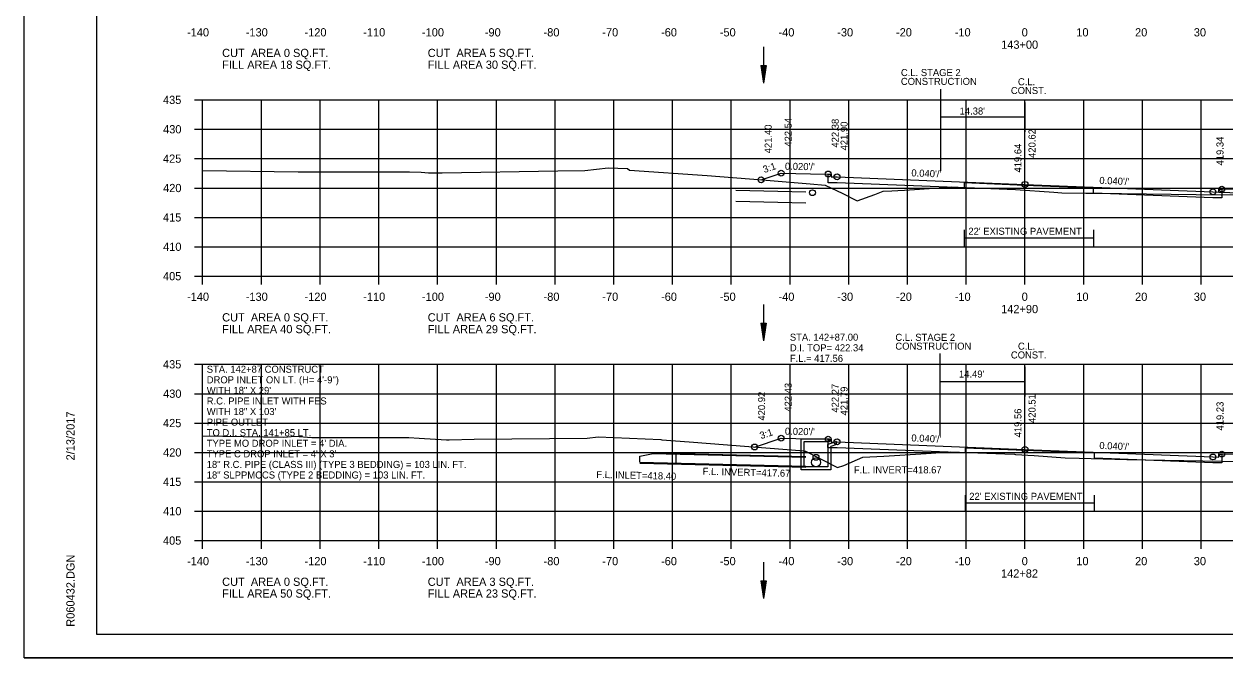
# Model space of a CAD drawing. Extents: x 1538688 to 1540766, y 656250 to 671912.
# Drawn here: x 1538687.8 to 1538892.2, y 662738 to 662845.9 of the extents above; entities that cross this region are included whole.
import ezdxf

# ---------------------------------------------------------------- set-up
doc = ezdxf.new("R2010")
doc.units = 0
for name, color, linetype in [('15', 7, 'Continuous'), ('16', 7, 'Continuous'), ('18', 7, 'Continuous'), ('20', 7, 'Continuous'), ('22', 7, 'Continuous'), ('26', 7, 'Continuous'), ('39', 7, 'Continuous'), ('40', 7, 'Continuous'), ('41', 7, 'Continuous'), ('42', 7, 'Continuous'), ('7', 7, 'Continuous'), ('Borings', 7, 'Continuous'), ('Default', 7, 'Continuous'), ('Horizontal Alignment', 7, 'Continuous'), ('RipRap', 7, 'Continuous'), ('Wall Heights', 7, 'Continuous')]:
    doc.layers.add(name, color=color, linetype=linetype)

msp = doc.modelspace()

# ---------------------------------------------------------------- linework, layer by layer
at = {"layer": '15'}
for p, q in [((1538813.19, 662838.88), (1538813.64, 662835.88)), ((1538813.19, 662838.88), (1538814.09, 662838.88)), ((1538813.27, 662838.88), (1538813.64, 662836.38)), ((1538813.34, 662838.88), (1538813.64, 662836.9)), ((1538813.42, 662838.88), (1538813.64, 662837.4)), ((1538813.5, 662838.88), (1538813.64, 662837.91)), ((1538813.57, 662838.88), (1538813.64, 662838.41)), ((1538814.09, 662838.88), (1538813.64, 662835.88)), ((1538813.79, 662838.88), (1538813.64, 662837.91)), ((1538813.94, 662838.88), (1538813.64, 662836.9)), ((1538814.02, 662838.88), (1538813.64, 662836.38)), ((1538813.87, 662838.88), (1538813.64, 662837.4)), ((1538813.71, 662838.88), (1538813.64, 662838.41)), ((1538813.19, 662795.03), (1538813.64, 662792.03)), ((1538813.19, 662795.03), (1538814.09, 662795.03)), ((1538813.27, 662795.03), (1538813.64, 662792.53)), ((1538813.34, 662795.03), (1538813.64, 662793.05)), ((1538813.42, 662795.03), (1538813.64, 662793.55)), ((1538813.5, 662795.03), (1538813.64, 662794.06)), ((1538813.57, 662795.03), (1538813.64, 662794.56)), ((1538814.09, 662795.03), (1538813.64, 662792.03)), ((1538813.79, 662795.03), (1538813.64, 662794.06)), ((1538813.94, 662795.03), (1538813.64, 662793.05)), ((1538814.02, 662795.03), (1538813.64, 662792.53)), ((1538813.87, 662795.03), (1538813.64, 662793.55)), ((1538813.71, 662795.03), (1538813.64, 662794.56)), ((1538813.19, 662751.18), (1538813.64, 662748.18)), ((1538813.19, 662751.18), (1538814.09, 662751.18)), ((1538813.27, 662751.18), (1538813.64, 662748.68)), ((1538813.34, 662751.18), (1538813.64, 662749.2)), ((1538813.42, 662751.18), (1538813.64, 662749.7)), ((1538813.5, 662751.18), (1538813.64, 662750.21)), ((1538813.57, 662751.18), (1538813.64, 662750.71)), ((1538814.09, 662751.18), (1538813.64, 662748.18)), ((1538813.79, 662751.18), (1538813.64, 662750.21)), ((1538813.94, 662751.18), (1538813.64, 662749.2)), ((1538814.02, 662751.18), (1538813.64, 662748.68)), ((1538813.87, 662751.18), (1538813.64, 662749.7)), ((1538813.71, 662751.18), (1538813.64, 662750.71))]:
    msp.add_line(p, q, dxfattribs=at)
at = {"layer": '16'}
msp.add_line((1538891.17, 662817.34), (1538925.16, 662816.16), dxfattribs=at)
at = {"layer": '18'}
for points in [[(1538718.18, 662821.03), (1538734.47, 662820.8), (1538735.14, 662820.79), (1538750.7, 662820.8), (1538753.39, 662820.79), (1538755.36, 662820.69), (1538756.64, 662820.61), (1538758.95, 662820.61), (1538778.67, 662820.97), (1538783.26, 662821.01), (1538787.23, 662821.45), (1538790.5, 662821.32), (1538790.83, 662821.07), (1538804.08, 662820.16), (1538813.43, 662819.41), (1538821.6, 662818.76), (1538824.17, 662818.53), (1538827.17, 662817.08), (1538829.59, 662815.83), (1538832.63, 662816.89), (1538834.01, 662817.49), (1538835.52, 662817.55), (1538836.56, 662817.61), (1538837.65, 662817.68), (1538844.43, 662818.12), (1538845.66, 662818.2), (1538846.3, 662818.18), (1538846.78, 662818.16), (1538856.58, 662817.78), (1538863.11, 662817.29), (1538864.43, 662817.19), (1538868.56, 662817.13), (1538870.34, 662817.12), (1538891.58, 662816.88), (1538896.28, 662816.9)], [(1538718.18, 662775.82), (1538732.01, 662775.63), (1538733.86, 662775.79), (1538736.79, 662775.55), (1538744.78, 662775.58), (1538753.3, 662775.55), (1538755.02, 662775.47), (1538759.67, 662775.19), (1538760.15, 662775.19), (1538764.42, 662775.27), (1538783.64, 662775.45), (1538785.54, 662775.66), (1538796.21, 662775.23), (1538796.33, 662775.14), (1538800.99, 662774.83), (1538820.57, 662773.27), (1538820.72, 662773.26), (1538820.76, 662773.26), (1538820.82, 662773.23), (1538826.26, 662770.43), (1538827.36, 662770.81), (1538830.6, 662772.23), (1538834.14, 662772.37), (1538834.14, 662772.37), (1538834.16, 662772.37), (1538841.37, 662772.84), (1538845.51, 662773.12), (1538854.76, 662772.76), (1538856.38, 662772.7), (1538856.54, 662772.68), (1538859.73, 662772.48), (1538865.01, 662772.1), (1538867.42, 662772.05), (1538875.53, 662771.81), (1538891.71, 662771.56), (1538891.71, 662771.56), (1538891.75, 662771.56), (1538896.96, 662771.45)]]:
    msp.add_lwpolyline(points, dxfattribs=at)
at = {"layer": '20'}
for points in [[(1538813.25, 662819.42), (1538816.67, 662820.56), (1538821.67, 662820.46), (1538824.67, 662820.4), (1538825.17, 662820.4), (1538825.18, 662819.9), (1538826.18, 662819.92), (1538858.18, 662818.64), (1538890.18, 662817.36), (1538891.18, 662817.34), (1538891.19, 662817.84), (1538891.69, 662817.84), (1538894.69, 662817.9), (1538899.69, 662818), (1538903.26, 662816.81)], [(1538812.14, 662773.94), (1538816.67, 662775.45), (1538821.67, 662775.35), (1538824.67, 662775.29), (1538825.17, 662775.29), (1538825.18, 662774.79), (1538826.18, 662774.81), (1538858.18, 662773.53), (1538890.18, 662772.25), (1538891.18, 662772.23), (1538891.19, 662772.73), (1538891.69, 662772.73), (1538894.69, 662772.79), (1538899.69, 662772.89), (1538906.23, 662770.71)]]:
    msp.add_lwpolyline(points, dxfattribs=at)
at = {"layer": '22'}
for p, q in [((1538718.18, 662833.02), (1538998.18, 662833.02)), ((1538718.18, 662803.02), (1538718.18, 662833.02)), ((1538728.18, 662803.02), (1538728.18, 662833.02)), ((1538738.18, 662803.02), (1538738.18, 662833.02)), ((1538748.18, 662803.02), (1538748.18, 662833.02)), ((1538758.18, 662803.02), (1538758.18, 662833.02)), ((1538768.18, 662803.02), (1538768.18, 662833.02)), ((1538778.18, 662803.02), (1538778.18, 662833.02)), ((1538788.18, 662803.02), (1538788.18, 662833.02)), ((1538798.18, 662803.02), (1538798.18, 662833.02)), ((1538808.18, 662803.02), (1538808.18, 662833.02)), ((1538818.18, 662803.02), (1538818.18, 662833.02)), ((1538828.18, 662803.02), (1538828.18, 662833.02)), ((1538838.18, 662803.02), (1538838.18, 662833.02)), ((1538848.18, 662803.02), (1538848.18, 662833.02)), ((1538858.18, 662803.02), (1538858.18, 662833.02)), ((1538868.18, 662803.02), (1538868.18, 662833.02)), ((1538878.18, 662803.02), (1538878.18, 662833.02)), ((1538888.18, 662803.02), (1538888.18, 662833.02)), ((1538718.18, 662828.02), (1538998.18, 662828.02)), ((1538718.18, 662823.02), (1538998.18, 662823.02)), ((1538718.18, 662818.02), (1538998.18, 662818.02)), ((1538718.18, 662813.02), (1538998.18, 662813.02)), ((1538718.18, 662808.02), (1538998.18, 662808.02)), ((1538718.18, 662803.02), (1538998.18, 662803.02)), ((1538718.18, 662788.02), (1538998.18, 662788.02)), ((1538718.18, 662758.02), (1538718.18, 662788.02)), ((1538728.18, 662758.02), (1538728.18, 662788.02)), ((1538738.18, 662758.02), (1538738.18, 662788.02)), ((1538748.18, 662758.02), (1538748.18, 662788.02)), ((1538758.18, 662758.02), (1538758.18, 662788.02)), ((1538768.18, 662758.02), (1538768.18, 662788.02)), ((1538778.18, 662758.02), (1538778.18, 662788.02)), ((1538788.18, 662758.02), (1538788.18, 662788.02)), ((1538798.18, 662758.02), (1538798.18, 662788.02)), ((1538808.18, 662758.02), (1538808.18, 662788.02)), ((1538818.18, 662758.02), (1538818.18, 662788.02)), ((1538828.18, 662758.02), (1538828.18, 662788.02)), ((1538838.18, 662758.02), (1538838.18, 662788.02)), ((1538848.18, 662758.02), (1538848.18, 662788.02)), ((1538858.18, 662758.02), (1538858.18, 662788.02)), ((1538868.18, 662758.02), (1538868.18, 662788.02)), ((1538878.18, 662758.02), (1538878.18, 662788.02)), ((1538888.18, 662758.02), (1538888.18, 662788.02)), ((1538718.18, 662783.02), (1538998.18, 662783.02)), ((1538718.18, 662778.02), (1538998.18, 662778.02)), ((1538718.18, 662773.02), (1538998.18, 662773.02)), ((1538718.18, 662768.02), (1538998.18, 662768.02)), ((1538718.18, 662763.02), (1538998.18, 662763.02)), ((1538718.18, 662758.02), (1538998.18, 662758.02))]:
    msp.add_line(p, q, dxfattribs=at)
at = {"layer": '26'}
for p, q in [((1538808.96, 662817.64), (1538820.85, 662817.35)), ((1538808.96, 662815.81), (1538820.85, 662815.52)), ((1538792.62, 662773.03), (1538820.85, 662772.35)), ((1538792.62, 662771.2), (1538820.85, 662770.52)), ((1538687.78, 662738.04), (1539021.11, 662738.04))]:
    msp.add_line(p, q, dxfattribs=at)
msp.add_lwpolyline([(1538687.77, 662951.37), (1539021.11, 662951.37), (1539021.11, 662738.04), (1538687.77, 662738.04)], close=True, dxfattribs=at)
for centre in [(1538813.25, 662819.42), (1538816.67, 662820.56), (1538824.67, 662820.4), (1538826.18, 662819.92), (1538858.18, 662818.64), (1538890.18, 662817.36), (1538891.69, 662817.84), (1538816.67, 662775.45), (1538824.67, 662775.29), (1538826.18, 662774.81), (1538812.14, 662773.94), (1538858.18, 662773.53), (1538891.69, 662772.73), (1538890.18, 662772.25)]:
    msp.add_circle(centre, 0.5, dxfattribs=at)
at = {"layer": '39'}
for p, q in [((1538813.64, 662842.07), (1538813.64, 662835.88)), ((1538813.64, 662798.22), (1538813.64, 662792.03)), ((1538820.1, 662775.36), (1538824.85, 662775.36)), ((1538820.1, 662773.86), (1538820.1, 662775.36)), ((1538820.6, 662773.86), (1538820.6, 662774.86)), ((1538820.6, 662774.86), (1538824.6, 662774.86)), ((1538824.93, 662775.2), (1538824.6, 662774.86)), ((1538826.1, 662774.88), (1538824.6, 662774.36)), ((1538824.93, 662775.2), (1538824.85, 662775.36)), ((1538794.72, 662772.82), (1538820.85, 662772.19)), ((1538824.6, 662773.86), (1538824.6, 662774.36)), ((1538824.68, 662774.01), (1538824.68, 662774.51)), ((1538826.1, 662774.35), (1538825.1, 662774.01)), ((1538825.1, 662773.86), (1538825.1, 662774.01)), ((1538792.62, 662771.37), (1538820.85, 662770.69)), ((1538813.64, 662754.37), (1538813.64, 662748.18))]:
    msp.add_line(p, q, dxfattribs=at)
for points in [[(1538826.1, 662774.35), (1538826.1, 662774.88)], [(1538792.62, 662771.37), (1538792.59, 662772.37), (1538794.88, 662772.83), (1538798.72, 662772.76), (1538798.76, 662771.26)], [(1538825.1, 662773.86), (1538825.1, 662770.08), (1538822.6, 662770.08), (1538820.1, 662770.08), (1538820.1, 662773.86)], [(1538824.6, 662773.86), (1538824.6, 662770.58), (1538822.6, 662770.58), (1538820.6, 662770.58), (1538820.6, 662773.86)]]:
    msp.add_lwpolyline(points, dxfattribs=at)
for centre, radius in [((1538822, 662817.22), 0.5), ((1538822.6, 662771.33), 0.75), ((1538822.6, 662772.19), 0.5)]:
    msp.add_circle(centre, radius, dxfattribs=at)
at = {"layer": '7'}
for p, q in [((1538847.84, 662810.88), (1538847.84, 662808.13)), ((1538869.84, 662810.88), (1538869.84, 662808.13)), ((1538869.84, 662809.5), (1538847.84, 662809.5)), ((1538847.98, 662765.76), (1538847.98, 662763.01)), ((1538869.98, 662765.76), (1538869.98, 662763.01)), ((1538869.98, 662764.39), (1538847.98, 662764.39))]:
    msp.add_line(p, q, dxfattribs=at)
at = {"layer": 'Borings'}
for p, q in [((1538716.78, 662833.02), (1538718.18, 662833.02)), ((1538718.18, 662803.02), (1538718.18, 662833.02)), ((1538716.78, 662828.02), (1538718.18, 662828.02)), ((1538716.78, 662823.02), (1538718.18, 662823.02)), ((1538716.78, 662818.02), (1538718.18, 662818.02)), ((1538716.78, 662813.02), (1538718.18, 662813.02)), ((1538716.78, 662808.02), (1538718.18, 662808.02)), ((1538716.78, 662803.02), (1538718.18, 662803.02)), ((1538718.18, 662803.02), (1538998.18, 662803.02)), ((1538718.18, 662801.62), (1538718.18, 662803.02)), ((1538728.18, 662801.62), (1538728.18, 662803.02)), ((1538738.18, 662801.62), (1538738.18, 662803.02)), ((1538748.18, 662801.62), (1538748.18, 662803.02)), ((1538758.18, 662801.62), (1538758.18, 662803.02)), ((1538768.18, 662801.62), (1538768.18, 662803.02)), ((1538778.18, 662801.62), (1538778.18, 662803.02)), ((1538788.18, 662801.62), (1538788.18, 662803.02)), ((1538798.18, 662801.62), (1538798.18, 662803.02)), ((1538808.18, 662801.62), (1538808.18, 662803.02)), ((1538818.18, 662801.62), (1538818.18, 662803.02)), ((1538828.18, 662801.62), (1538828.18, 662803.02)), ((1538838.18, 662801.62), (1538838.18, 662803.02)), ((1538848.18, 662801.62), (1538848.18, 662803.02)), ((1538858.18, 662801.62), (1538858.18, 662803.02)), ((1538868.18, 662801.62), (1538868.18, 662803.02)), ((1538878.18, 662801.62), (1538878.18, 662803.02)), ((1538888.18, 662801.62), (1538888.18, 662803.02)), ((1538716.78, 662788.02), (1538718.18, 662788.02)), ((1538718.18, 662758.02), (1538718.18, 662788.02)), ((1538716.78, 662783.02), (1538718.18, 662783.02)), ((1538716.78, 662778.02), (1538718.18, 662778.02)), ((1538716.78, 662773.02), (1538718.18, 662773.02)), ((1538716.78, 662768.02), (1538718.18, 662768.02)), ((1538716.78, 662763.02), (1538718.18, 662763.02)), ((1538716.78, 662758.02), (1538718.18, 662758.02)), ((1538718.18, 662758.02), (1538998.18, 662758.02)), ((1538718.18, 662756.62), (1538718.18, 662758.02)), ((1538728.18, 662756.62), (1538728.18, 662758.02)), ((1538738.18, 662756.62), (1538738.18, 662758.02)), ((1538748.18, 662756.62), (1538748.18, 662758.02)), ((1538758.18, 662756.62), (1538758.18, 662758.02)), ((1538768.18, 662756.62), (1538768.18, 662758.02)), ((1538778.18, 662756.62), (1538778.18, 662758.02)), ((1538788.18, 662756.62), (1538788.18, 662758.02)), ((1538798.18, 662756.62), (1538798.18, 662758.02)), ((1538808.18, 662756.62), (1538808.18, 662758.02)), ((1538818.18, 662756.62), (1538818.18, 662758.02)), ((1538828.18, 662756.62), (1538828.18, 662758.02)), ((1538838.18, 662756.62), (1538838.18, 662758.02)), ((1538848.18, 662756.62), (1538848.18, 662758.02)), ((1538858.18, 662756.62), (1538858.18, 662758.02)), ((1538868.18, 662756.62), (1538868.18, 662758.02)), ((1538878.18, 662756.62), (1538878.18, 662758.02)), ((1538888.18, 662756.62), (1538888.18, 662758.02))]:
    msp.add_line(p, q, dxfattribs=at)
at = {"layer": 'Default'}
for p, q in [((1538843.8, 662834.86), (1538843.8, 662820.95)), ((1538858.18, 662832.56), (1538858.18, 662827.56)), ((1538858.18, 662830.06), (1538843.8, 662830.06)), ((1538843.69, 662789.86), (1538843.69, 662775.95)), ((1538858.18, 662787.56), (1538858.18, 662782.56)), ((1538858.18, 662785.06), (1538843.69, 662785.06))]:
    msp.add_line(p, q, dxfattribs=at)
at = {"layer": 'RipRap'}
for p, q in [((1538700.18, 662742.02), (1538700.18, 662947.48)), ((1538700.18, 662742.02), (1538700.18, 662742.02)), ((1539016.36, 662742.02), (1538700.18, 662742.02))]:
    msp.add_line(p, q, dxfattribs=at)
at = {"layer": 'Wall Heights'}
for points in [[(1538891.69, 662817.84), (1538891.69, 662816.34), (1538890.18, 662816.36), (1538869.85, 662817.17), (1538869.85, 662818), (1538858.18, 662818.47), (1538847.85, 662818.88), (1538847.85, 662818.05), (1538826.18, 662818.92), (1538824.67, 662818.9), (1538824.67, 662820.4)], [(1538891.69, 662772.73), (1538891.69, 662771.23), (1538890.18, 662771.25), (1538869.99, 662772.06), (1538869.99, 662772.89), (1538858.18, 662773.36), (1538847.99, 662773.77), (1538847.99, 662772.94), (1538826.18, 662773.81), (1538824.67, 662773.79), (1538824.67, 662775.29)]]:
    msp.add_lwpolyline(points, dxfattribs=at)

# ---------------------------------------------------------------- texts
at = {"layer": '40'}
for s, p in [('STA. 142+87.00', (1538818.15, 662792.03)), ('D.I. TOP= 422.34', (1538818.15, 662790.23)), ('F.L.= 417.56', (1538818.15, 662788.43)), ('STA. 142+87 CONSTRUCT', (1538718.88, 662786.58)), ('DROP INLET ON LT. (H= 4\'-9")', (1538718.88, 662784.78)), ('WITH 18" X 29\'', (1538718.88, 662782.98)), ('R.C. PIPE INLET WITH FES ', (1538718.88, 662781.18)), ('WITH 18" X 103\'', (1538718.88, 662779.38)), ('TO D.I. STA. 141+85 LT.', (1538718.88, 662775.78)), ('PIPE OUTLET', (1538718.88, 662777.58)), ("TYPE MO DROP INLET = 4' DIA.", (1538718.88, 662773.98)), ("TYPE C DROP INLET = 4' X 3'", (1538718.88, 662772.18)), ('18" R.C. PIPE (CLASS III) (TYPE 3 BEDDING) = 103 LIN. FT.', (1538718.88, 662770.38)), ('18" SLPPMCCS (TYPE 2 BEDDING) = 103 LIN. FT.', (1538718.88, 662768.58)), ('F.L. INVERT=418.67', (1538829.05, 662769.45))]:
    msp.add_text(s, height=1.2, dxfattribs=at).set_placement(p)
for s, p in [('F.L. INLET=418.40', (1538785.19, 662768.69)), ('F.L. INVERT=417.67', (1538803.29, 662769.22))]:
    msp.add_text(s, height=1.2, rotation=358.616, dxfattribs=at).set_placement(p)
at = {"layer": '41'}
for s, p in [('421.40', (1538815.05, 662823.92)), ('422.54', (1538818.47, 662825.06)), ('422.38', (1538826.47, 662824.9)), ('421.90', (1538827.98, 662824.42)), ('420.62', (1538859.98, 662823.14)), ('419.34', (1538891.98, 662821.86)), ('419.64', (1538857.58, 662820.66)), ('420.92', (1538813.94, 662778.44)), ('422.43', (1538818.47, 662779.95)), ('422.27', (1538826.47, 662779.79)), ('421.79', (1538827.98, 662779.31)), ('420.51', (1538859.98, 662778.03)), ('419.23', (1538891.98, 662776.75)), ('419.56', (1538857.58, 662775.58))]:
    msp.add_text(s, height=1.2, rotation=90, dxfattribs=at).set_placement(p)
at = {"layer": '42'}
for s, rotation, p in [('3:1', 18.4349, (1538813.8, 662820.56)), ("0.020'/'", 358.8542, (1538817.3, 662821.14)), ("0.040'/'", 357.7094, (1538838.82, 662820.01)), ("0.040'/'", 357.7094, (1538870.82, 662818.73)), ('3:1', 18.4349, (1538813.25, 662775.27)), ("0.020'/'", 358.8542, (1538817.3, 662776.04)), ("0.040'/'", 357.7094, (1538838.82, 662774.9)), ("0.040'/'", 357.7094, (1538870.82, 662773.62))]:
    msp.add_text(s, height=1.2, rotation=rotation, dxfattribs=at).set_placement(p)
at = {"layer": '7'}
for p in [(1538848.54, 662810.06), (1538848.69, 662764.95)]:
    msp.add_text("22' EXISTING PAVEMENT", height=1.2, dxfattribs=at).set_placement(p)
at = {"layer": 'Default'}
for s, p in [('C.L. STAGE 2', (1538837.06, 662837.07)), ('CONSTRUCTION', (1538837.05, 662835.57)), ('C.L.', (1538856.98, 662835.51)), ('CONST.', (1538855.78, 662834.01)), ("14.38'", (1538847.05, 662830.52)), ('CONSTRUCTION', (1538836.11, 662790.51)), ('C.L. STAGE 2', (1538836.12, 662792.01)), ('C.L.', (1538856.98, 662790.51)), ('CONST.', (1538855.78, 662789.01)), ("14.49'", (1538846.94, 662785.76))]:
    msp.add_text(s, height=1.2, dxfattribs=at).set_placement(p)
at = {"layer": 'Horizontal Alignment'}
for s, p in [('-140', (1538715.52, 662843.82)), ('-130', (1538725.52, 662843.82)), ('-120', (1538735.52, 662843.82)), ('-110', (1538745.52, 662843.82)), ('-100', (1538755.52, 662843.82)), ('-90', (1538766.22, 662843.82)), ('-80', (1538776.22, 662843.82)), ('-70', (1538786.22, 662843.82)), ('-60', (1538796.22, 662843.82)), ('-50', (1538806.22, 662843.82)), ('-40', (1538816.22, 662843.82)), ('-30', (1538826.22, 662843.82)), ('-20', (1538836.22, 662843.82)), ('-10', (1538846.22, 662843.82)), ('0', (1538857.62, 662843.82)), ('10', (1538866.92, 662843.82)), ('20', (1538876.92, 662843.82)), ('30', (1538886.92, 662843.82)), ('143+00', (1538854.12, 662841.72)), ('CUT  AREA 0 SQ.FT.', (1538721.5, 662840.31)), ('CUT  AREA 5 SQ.FT.', (1538756.5, 662840.31)), ('FILL AREA 18 SQ.FT.', (1538721.5, 662838.31)), ('FILL AREA 30 SQ.FT.', (1538756.5, 662838.31)), ('435', (1538711.43, 662832.32)), ('430', (1538711.45, 662827.32)), ('425', (1538711.43, 662822.32)), ('420', (1538711.45, 662817.32)), ('415', (1538711.43, 662812.32)), ('410', (1538711.45, 662807.32)), ('405', (1538711.43, 662802.32)), ('-140', (1538715.52, 662798.82)), ('-130', (1538725.52, 662798.82)), ('-120', (1538735.52, 662798.82)), ('-110', (1538745.52, 662798.82)), ('-100', (1538755.52, 662798.82)), ('-90', (1538766.22, 662798.82)), ('-80', (1538776.22, 662798.82)), ('-70', (1538786.22, 662798.82)), ('-60', (1538796.22, 662798.82)), ('-50', (1538806.22, 662798.82)), ('-40', (1538816.22, 662798.82)), ('-30', (1538826.22, 662798.82)), ('-20', (1538836.22, 662798.82)), ('-10', (1538846.22, 662798.82)), ('0', (1538857.62, 662798.82)), ('10', (1538866.92, 662798.82)), ('20', (1538876.92, 662798.82)), ('30', (1538886.92, 662798.82)), ('142+90', (1538854.12, 662796.72)), ('CUT  AREA 0 SQ.FT.', (1538721.5, 662795.31)), ('CUT  AREA 6 SQ.FT.', (1538756.5, 662795.31)), ('FILL AREA 40 SQ.FT.', (1538721.5, 662793.31)), ('FILL AREA 29 SQ.FT.', (1538756.5, 662793.31)), ('435', (1538711.43, 662787.32)), ('430', (1538711.45, 662782.32)), ('425', (1538711.43, 662777.32)), ('420', (1538711.45, 662772.32)), ('415', (1538711.43, 662767.32)), ('410', (1538711.45, 662762.32)), ('405', (1538711.43, 662757.32)), ('-140', (1538715.52, 662753.82)), ('-130', (1538725.52, 662753.82)), ('-120', (1538735.52, 662753.82)), ('-110', (1538745.52, 662753.82)), ('-100', (1538755.52, 662753.82)), ('-90', (1538766.22, 662753.82)), ('-80', (1538776.22, 662753.82)), ('-70', (1538786.22, 662753.82)), ('-60', (1538796.22, 662753.82)), ('-50', (1538806.22, 662753.82)), ('-40', (1538816.22, 662753.82)), ('-30', (1538826.22, 662753.82)), ('-20', (1538836.22, 662753.82)), ('-10', (1538846.22, 662753.82)), ('0', (1538857.62, 662753.82)), ('10', (1538866.92, 662753.82)), ('20', (1538876.92, 662753.82)), ('30', (1538886.92, 662753.82)), ('142+82', (1538854.1, 662751.72)), ('CUT  AREA 0 SQ.FT.', (1538721.5, 662750.31)), ('CUT  AREA 3 SQ.FT.', (1538756.5, 662750.31)), ('FILL AREA 50 SQ.FT.', (1538721.5, 662748.31)), ('FILL AREA 23 SQ.FT.', (1538756.5, 662748.31))]:
    msp.add_text(s, height=1.4, dxfattribs=at).set_placement(p)
at = {"layer": 'RipRap'}
for s, p in [('2/13/2017', (1538696.37, 662771.66)), ('R060432.DGN', (1538696.37, 662743.35))]:
    msp.add_text(s, height=1.4, rotation=90, dxfattribs=at).set_placement(p)

doc.saveas('drawing.dxf')
